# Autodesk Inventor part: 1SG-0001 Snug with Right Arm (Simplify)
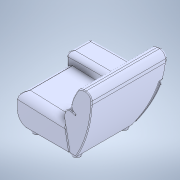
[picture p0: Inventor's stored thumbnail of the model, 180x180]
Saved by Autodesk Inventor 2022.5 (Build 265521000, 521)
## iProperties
Created: 2025-08
Part Number: 1SG-0001 Snug with Right Arm (Simplify)
Material: Generic
Document SubType Name: Modeling
Designer: Mark.Glazzard
Density: 1 g/cm^3
Appearance: Default
Author: Mark.Glazzard
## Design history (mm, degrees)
derived "1SG-0001 Snug with Right Arm (Simplify) 2022.iam"
body "Solid1"
body "Solid2"
body "Solid3"
body "Solid4"
body "Solid5"
body "Solid6"
body "Solid7"
